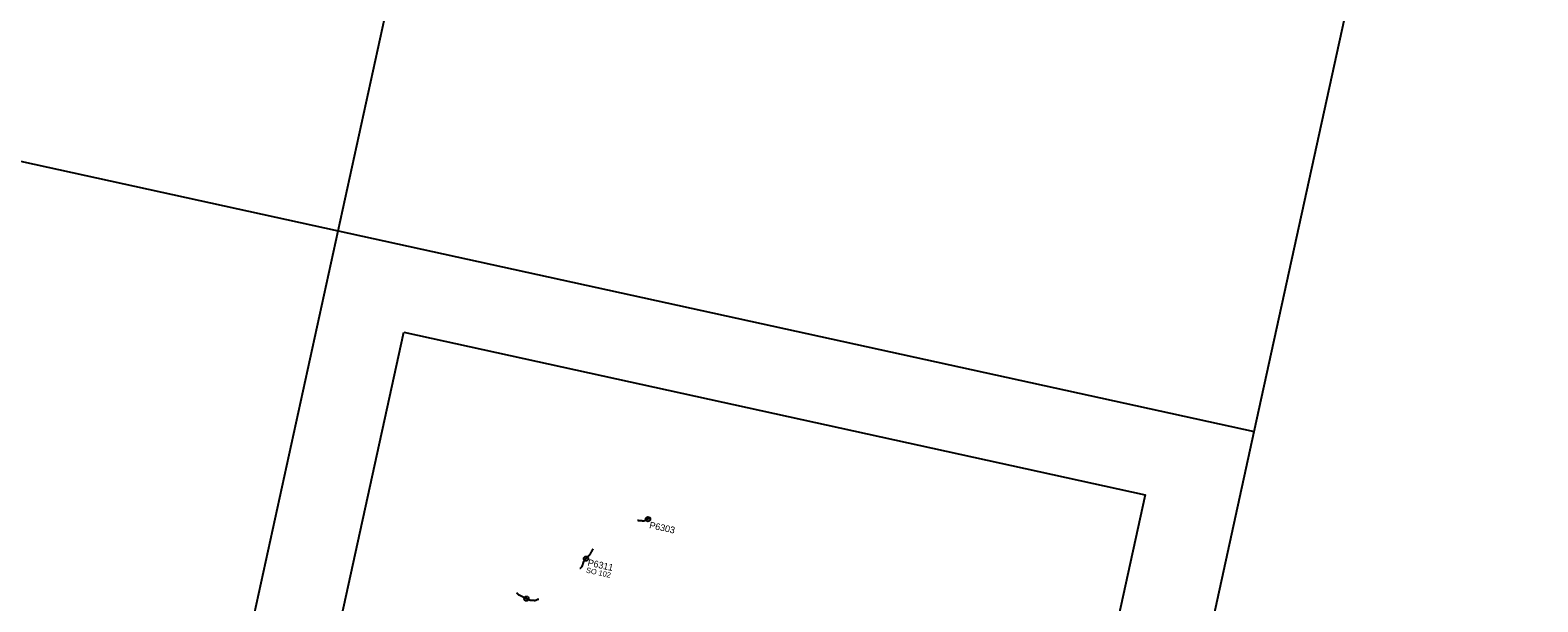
# Model space of a CAD drawing. Extents: x -748502 to -746324, y -1132034 to -1131005.
# Drawn here: x -746661.5 to -746323.8, y -1131782.1 to -1131654.1 of the extents above; entities that cross this region are included whole.
import ezdxf

# ---------------------------------------------------------------- set-up
doc = ezdxf.new("R2010")
doc.units = 0
for name, color, linetype in [('ram', 7, 'Continuous'), ('Rozpiska_pole_1', 7, 'Continuous'), ('SCHEMA_POP', 7, 'Continuous')]:
    doc.layers.add(name, color=color, linetype=linetype)

msp = doc.modelspace()

# ---------------------------------------------------------------- linework, layer by layer
at = {"layer": 'ram'}
for p, q in [((-746592.45, -1131699.01), (-746528.92, -1131408.88)), ((-746387.31, -1131743.92), (-746323.78, -1131453.8)), ((-746797.59, -1131654.09), (-746592.45, -1131699.01)), ((-746797.59, -1131654.09), (-746592.45, -1131699.01)), ((-746655.98, -1131989.13), (-746592.45, -1131699.01)), ((-746592.45, -1131699.01), (-746387.31, -1131743.92)), ((-746592.45, -1131699.01), (-746387.31, -1131743.92)), ((-746450.84, -1132034.05), (-746387.31, -1131743.92))]:
    msp.add_line(p, q, dxfattribs=at)
at = {"layer": 'Rozpiska_pole_1'}
msp.add_lwpolyline([(-746577.79, -1131721.7), (-746411.72, -1131758.07), (-746467.34, -1132012.05), (-746633.4, -1131975.69)], close=True, dxfattribs=at)
at = {"layer": 'SCHEMA_POP'}
for p, q in [((-746523.4, -1131763.74), (-746523.42, -1131763.75)), ((-746536.37, -1131771.78), (-746536.39, -1131771.8)), ((-746552.45, -1131780.04), (-746552.46, -1131780.01))]:
    msp.add_line(p, q, dxfattribs=at)
for points in [[(-746524.35, -1131763.97), (-746524.39, -1131763.96), (-746524.44, -1131763.96), (-746524.48, -1131763.95), (-746524.52, -1131763.95), (-746524.57, -1131763.95), (-746524.61, -1131763.94), (-746524.65, -1131763.94), (-746524.7, -1131763.93), (-746524.74, -1131763.93), (-746524.78, -1131763.92), (-746524.82, -1131763.92), (-746524.87, -1131763.92), (-746524.92, -1131763.91), (-746524.93, -1131763.91), (-746524.95, -1131763.91), (-746524.95, -1131763.91), (-746524.98, -1131763.9), (-746525.01, -1131763.9), (-746525.05, -1131763.9), (-746525.08, -1131763.89), (-746525.12, -1131763.89), (-746525.16, -1131763.89), (-746525.17, -1131763.89), (-746525.2, -1131763.88), (-746525.25, -1131763.88), (-746525.29, -1131763.87), (-746525.34, -1131763.87), (-746525.38, -1131763.86), (-746525.41, -1131763.86)], [(-746523.68, -1131763.89), (-746523.71, -1131763.9), (-746523.74, -1131763.91), (-746523.76, -1131763.92), (-746523.79, -1131763.93), (-746523.82, -1131763.94), (-746523.85, -1131763.95), (-746523.87, -1131763.95), (-746523.9, -1131763.96), (-746523.93, -1131763.96), (-746523.96, -1131763.97), (-746523.99, -1131763.97), (-746524.02, -1131763.98), (-746524.05, -1131763.98), (-746524.08, -1131763.98), (-746524.11, -1131763.98), (-746524.14, -1131763.98), (-746524.17, -1131763.98), (-746524.2, -1131763.98), (-746524.23, -1131763.98), (-746524.26, -1131763.98), (-746524.28, -1131763.97), (-746524.31, -1131763.97), (-746524.34, -1131763.97), (-746524.35, -1131763.97)], [(-746523.62, -1131763.86), (-746523.66, -1131763.88), (-746523.68, -1131763.88), (-746523.68, -1131763.89)], [(-746523.42, -1131763.75), (-746523.45, -1131763.77), (-746523.47, -1131763.79), (-746523.5, -1131763.8), (-746523.52, -1131763.81), (-746523.54, -1131763.82), (-746523.57, -1131763.84), (-746523.6, -1131763.85), (-746523.62, -1131763.86)], [(-746523.35, -1131763.71), (-746523.38, -1131763.73), (-746523.4, -1131763.74), (-746523.4, -1131763.74)], [(-746523.23, -1131763.64), (-746523.25, -1131763.65), (-746523.26, -1131763.65), (-746523.28, -1131763.66), (-746523.3, -1131763.68), (-746523.33, -1131763.7), (-746523.35, -1131763.71)], [(-746523.17, -1131763.6), (-746523.17, -1131763.6), (-746523.19, -1131763.61), (-746523.23, -1131763.64)], [(-746522.54, -1131763.21), (-746522.58, -1131763.23), (-746522.62, -1131763.26), (-746522.66, -1131763.28), (-746522.68, -1131763.3), (-746522.71, -1131763.31), (-746522.75, -1131763.33), (-746522.77, -1131763.35), (-746522.8, -1131763.37), (-746522.83, -1131763.39), (-746522.86, -1131763.41), (-746522.89, -1131763.42), (-746522.93, -1131763.45), (-746522.95, -1131763.46), (-746522.99, -1131763.49), (-746523.03, -1131763.51), (-746523.06, -1131763.53), (-746523.09, -1131763.55), (-746523.11, -1131763.56), (-746523.13, -1131763.58), (-746523.15, -1131763.59), (-746523.16, -1131763.59), (-746523.17, -1131763.6)], [(-746536.39, -1131771.8), (-746536.43, -1131771.83), (-746536.46, -1131771.87), (-746536.5, -1131771.9), (-746536.53, -1131771.94), (-746536.56, -1131771.97), (-746536.6, -1131772.01), (-746536.63, -1131772.04), (-746536.67, -1131772.08), (-746536.7, -1131772.11), (-746536.74, -1131772.15), (-746536.77, -1131772.18), (-746536.81, -1131772.22), (-746536.84, -1131772.25), (-746536.87, -1131772.29), (-746536.91, -1131772.32), (-746536.94, -1131772.35), (-746536.97, -1131772.39), (-746537.01, -1131772.42), (-746537.04, -1131772.45), (-746537.05, -1131772.46), (-746537.08, -1131772.5), (-746537.12, -1131772.53), (-746537.13, -1131772.55), (-746537.15, -1131772.57), (-746537.17, -1131772.59), (-746537.18, -1131772.6), (-746537.2, -1131772.62), (-746537.22, -1131772.64), (-746537.24, -1131772.66), (-746537.25, -1131772.67)], [(-746535.99, -1131771.25), (-746536, -1131771.28), (-746536.02, -1131771.32), (-746536.04, -1131771.35), (-746536.06, -1131771.38), (-746536.08, -1131771.4), (-746536.09, -1131771.43), (-746536.11, -1131771.45), (-746536.13, -1131771.48), (-746536.15, -1131771.51), (-746536.17, -1131771.54), (-746536.19, -1131771.57), (-746536.21, -1131771.59), (-746536.23, -1131771.62), (-746536.26, -1131771.65), (-746536.28, -1131771.68), (-746536.3, -1131771.7), (-746536.32, -1131771.73), (-746536.35, -1131771.75), (-746536.37, -1131771.78)], [(-746535.59, -1131770.51), (-746535.61, -1131770.55), (-746535.63, -1131770.59), (-746535.65, -1131770.62), (-746535.66, -1131770.65), (-746535.68, -1131770.69), (-746535.7, -1131770.72), (-746535.71, -1131770.75), (-746535.74, -1131770.79), (-746535.76, -1131770.83), (-746535.78, -1131770.87), (-746535.8, -1131770.91), (-746535.83, -1131770.96), (-746535.85, -1131771), (-746535.87, -1131771.03), (-746535.88, -1131771.06), (-746535.9, -1131771.1), (-746535.93, -1131771.14), (-746535.95, -1131771.18), (-746535.97, -1131771.22), (-746535.99, -1131771.25)], [(-746535.42, -1131770.27), (-746535.44, -1131770.29), (-746535.46, -1131770.31), (-746535.47, -1131770.33), (-746535.49, -1131770.35), (-746535.5, -1131770.38), (-746535.52, -1131770.4), (-746535.54, -1131770.42), (-746535.55, -1131770.45), (-746535.56, -1131770.47), (-746535.58, -1131770.5), (-746535.59, -1131770.51)], [(-746538.29, -1131774.59), (-746538.31, -1131774.61), (-746538.33, -1131774.62), (-746538.35, -1131774.63)], [(-746537.82, -1131773.93), (-746537.82, -1131773.96), (-746537.83, -1131773.98), (-746537.84, -1131774.01), (-746537.85, -1131774.04), (-746537.86, -1131774.06), (-746537.88, -1131774.09), (-746537.89, -1131774.12), (-746537.9, -1131774.15), (-746537.92, -1131774.18), (-746537.93, -1131774.2), (-746537.94, -1131774.22), (-746537.95, -1131774.24), (-746537.96, -1131774.25), (-746537.98, -1131774.28), (-746538, -1131774.3), (-746538.02, -1131774.33), (-746538.04, -1131774.35), (-746538.05, -1131774.38), (-746538.07, -1131774.4), (-746538.1, -1131774.42), (-746538.12, -1131774.44), (-746538.14, -1131774.47), (-746538.16, -1131774.49), (-746538.18, -1131774.51), (-746538.2, -1131774.52), (-746538.22, -1131774.54), (-746538.24, -1131774.56), (-746538.27, -1131774.58), (-746538.29, -1131774.59)], [(-746537.57, -1131773.2), (-746537.59, -1131773.24), (-746537.59, -1131773.26), (-746537.6, -1131773.28), (-746537.61, -1131773.3), (-746537.62, -1131773.32), (-746537.63, -1131773.37), (-746537.64, -1131773.41), (-746537.65, -1131773.42), (-746537.66, -1131773.45), (-746537.67, -1131773.48), (-746537.68, -1131773.51), (-746537.69, -1131773.55), (-746537.7, -1131773.58), (-746537.71, -1131773.61), (-746537.72, -1131773.65), (-746537.74, -1131773.7), (-746537.75, -1131773.74), (-746537.76, -1131773.78), (-746537.78, -1131773.82), (-746537.79, -1131773.87), (-746537.81, -1131773.91), (-746537.82, -1131773.93)], [(-746537.25, -1131772.67), (-746537.28, -1131772.7), (-746537.29, -1131772.71), (-746537.3, -1131772.72), (-746537.32, -1131772.74), (-746537.34, -1131772.77), (-746537.36, -1131772.79), (-746537.38, -1131772.82), (-746537.4, -1131772.84), (-746537.42, -1131772.87), (-746537.43, -1131772.89), (-746537.45, -1131772.92), (-746537.47, -1131772.95), (-746537.48, -1131772.97), (-746537.49, -1131773), (-746537.51, -1131773.03), (-746537.52, -1131773.05), (-746537.53, -1131773.08), (-746537.54, -1131773.11), (-746537.55, -1131773.14), (-746537.56, -1131773.15), (-746537.56, -1131773.17), (-746537.57, -1131773.19), (-746537.57, -1131773.2)], [(-746551.88, -1131780.58), (-746551.9, -1131780.57), (-746551.91, -1131780.56), (-746551.93, -1131780.56), (-746551.95, -1131780.54), (-746551.98, -1131780.53), (-746551.99, -1131780.52), (-746552.01, -1131780.51), (-746552.03, -1131780.49), (-746552.05, -1131780.49), (-746552.07, -1131780.47), (-746552.09, -1131780.45), (-746552.11, -1131780.44), (-746552.13, -1131780.42), (-746552.15, -1131780.41), (-746552.17, -1131780.39), (-746552.18, -1131780.38), (-746552.2, -1131780.36), (-746552.22, -1131780.35), (-746552.24, -1131780.32), (-746552.26, -1131780.3), (-746552.28, -1131780.28), (-746552.29, -1131780.26), (-746552.31, -1131780.24), (-746552.33, -1131780.21), (-746552.35, -1131780.19), (-746552.37, -1131780.17), (-746552.38, -1131780.14), (-746552.4, -1131780.12), (-746552.41, -1131780.1), (-746552.42, -1131780.08), (-746552.43, -1131780.07), (-746552.44, -1131780.05), (-746552.45, -1131780.04)], [(-746549.66, -1131781.66), (-746549.7, -1131781.64), (-746549.75, -1131781.62), (-746549.79, -1131781.6), (-746549.83, -1131781.58), (-746549.88, -1131781.56), (-746549.92, -1131781.53), (-746549.97, -1131781.51), (-746550.01, -1131781.49), (-746550.06, -1131781.47), (-746550.1, -1131781.45), (-746550.14, -1131781.43), (-746550.18, -1131781.41), (-746550.22, -1131781.39), (-746550.26, -1131781.37), (-746550.3, -1131781.35), (-746550.31, -1131781.35), (-746550.35, -1131781.33), (-746550.39, -1131781.3), (-746550.44, -1131781.28), (-746550.48, -1131781.26), (-746550.53, -1131781.24), (-746550.57, -1131781.22), (-746550.62, -1131781.2), (-746550.64, -1131781.18), (-746550.66, -1131781.17), (-746550.69, -1131781.16), (-746550.71, -1131781.15), (-746550.74, -1131781.14), (-746550.76, -1131781.13), (-746550.78, -1131781.11), (-746550.81, -1131781.1), (-746550.83, -1131781.09), (-746550.85, -1131781.08), (-746550.89, -1131781.06), (-746550.94, -1131781.04), (-746550.98, -1131781.02), (-746551.01, -1131781.01), (-746551.03, -1131780.99), (-746551.06, -1131780.98), (-746551.08, -1131780.97), (-746551.12, -1131780.95), (-746551.17, -1131780.93), (-746551.21, -1131780.91), (-746551.25, -1131780.89), (-746551.27, -1131780.88), (-746551.29, -1131780.87), (-746551.32, -1131780.86), (-746551.36, -1131780.83), (-746551.41, -1131780.81), (-746551.44, -1131780.8), (-746551.47, -1131780.78), (-746551.49, -1131780.77), (-746551.52, -1131780.76), (-746551.57, -1131780.73), (-746551.62, -1131780.71), (-746551.66, -1131780.69), (-746551.71, -1131780.66), (-746551.76, -1131780.64), (-746551.8, -1131780.62), (-746551.85, -1131780.6), (-746551.88, -1131780.58)], [(-746549.42, -1131781.73), (-746549.45, -1131781.73), (-746549.48, -1131781.72), (-746549.5, -1131781.72), (-746549.53, -1131781.71), (-746549.56, -1131781.71), (-746549.59, -1131781.7), (-746549.61, -1131781.68), (-746549.63, -1131781.68), (-746549.65, -1131781.67), (-746549.66, -1131781.66)], [(-746548.51, -1131781.8), (-746548.52, -1131781.8), (-746548.53, -1131781.79), (-746548.59, -1131781.79), (-746548.64, -1131781.79), (-746548.69, -1131781.78), (-746548.75, -1131781.78), (-746548.8, -1131781.78), (-746548.85, -1131781.77), (-746548.91, -1131781.77), (-746548.96, -1131781.76), (-746549, -1131781.76), (-746549.01, -1131781.76), (-746549.03, -1131781.76), (-746549.05, -1131781.76), (-746549.1, -1131781.75), (-746549.15, -1131781.75), (-746549.2, -1131781.75), (-746549.25, -1131781.74), (-746549.3, -1131781.74), (-746549.34, -1131781.74), (-746549.38, -1131781.73), (-746549.41, -1131781.73), (-746549.41, -1131781.73), (-746549.42, -1131781.73)], [(-746547.54, -1131781.55), (-746547.55, -1131781.55), (-746547.57, -1131781.54), (-746547.6, -1131781.53), (-746547.61, -1131781.53), (-746547.63, -1131781.53), (-746547.65, -1131781.52), (-746547.68, -1131781.52), (-746547.69, -1131781.52), (-746547.72, -1131781.52), (-746547.74, -1131781.52), (-746547.76, -1131781.53), (-746547.78, -1131781.53), (-746547.8, -1131781.53), (-746547.82, -1131781.54), (-746547.84, -1131781.55), (-746547.86, -1131781.55), (-746547.87, -1131781.56), (-746547.89, -1131781.57), (-746547.91, -1131781.58), (-746547.93, -1131781.58), (-746547.94, -1131781.6), (-746547.96, -1131781.61), (-746547.98, -1131781.62), (-746547.99, -1131781.63), (-746548.04, -1131781.66), (-746548.07, -1131781.68), (-746548.09, -1131781.69), (-746548.11, -1131781.7), (-746548.12, -1131781.71), (-746548.14, -1131781.72), (-746548.16, -1131781.73), (-746548.18, -1131781.74), (-746548.19, -1131781.75), (-746548.21, -1131781.76), (-746548.24, -1131781.77), (-746548.26, -1131781.77), (-746548.28, -1131781.78), (-746548.3, -1131781.78), (-746548.32, -1131781.79), (-746548.34, -1131781.79), (-746548.35, -1131781.79), (-746548.38, -1131781.8), (-746548.4, -1131781.8), (-746548.42, -1131781.8), (-746548.43, -1131781.8), (-746548.45, -1131781.8), (-746548.47, -1131781.8), (-746548.5, -1131781.8), (-746548.51, -1131781.8)]]:
    msp.add_lwpolyline(points, dxfattribs=at)
for centre in [(-746523.09, -1131763.55), (-746536.97, -1131772.39), (-746550.28, -1131781.34)]:
    msp.add_circle(centre, 0.5, dxfattribs=at)

# ---------------------------------------------------------------- texts
for s, height, p in [('P6303', 1.5, (-746522.89, -1131765.56)), ('SO 102', 1.2, (-746537.04, -1131775.5)), ('P6311', 1.5, (-746536.7, -1131773.94))]:
    msp.add_text(s, height=height, rotation=347.649, dxfattribs=at).set_placement(p)

doc.saveas('drawing.dxf')
